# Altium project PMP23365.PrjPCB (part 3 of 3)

## Sheet PMP23365B_SH3.SchDoc
size 558 x 431 mm; Date: Not shown in title block; ApprovedBy: Not shown in title block; CheckedBy: Not shown in title block; Author: Not shown in title block; CompanyName: Not shown in title block; DrawnBy: D Xing; Engineer: Not shown in title block; Organization: Not shown in title block; Address1: Not shown in title block; Address2: Not shown in title block; Address3: Not shown in title block; Address4: Not shown in title block; DocumentNumber: 1; Revision: Use project parameter SCH_Rev; SheetNumber: 3; SheetTotal: 3; PageSetup: Record=PageOptions¦CenterHorizontal=True¦CenterVertical=True¦PrintScale=1.00¦XCorrection=1.00¦YCorrection=1.00¦PrintKind=0¦BorderSize=5000000¦LeftOffset=0¦BottomOffset=0¦Orientation=2¦PaperLength=1000¦PaperWidth=1000¦Scale=100¦PaperSource=15¦PrintQuality=600¦MediaType=1¦DitherType=10¦PaperKind=Letter¦PrintScaleMode=1
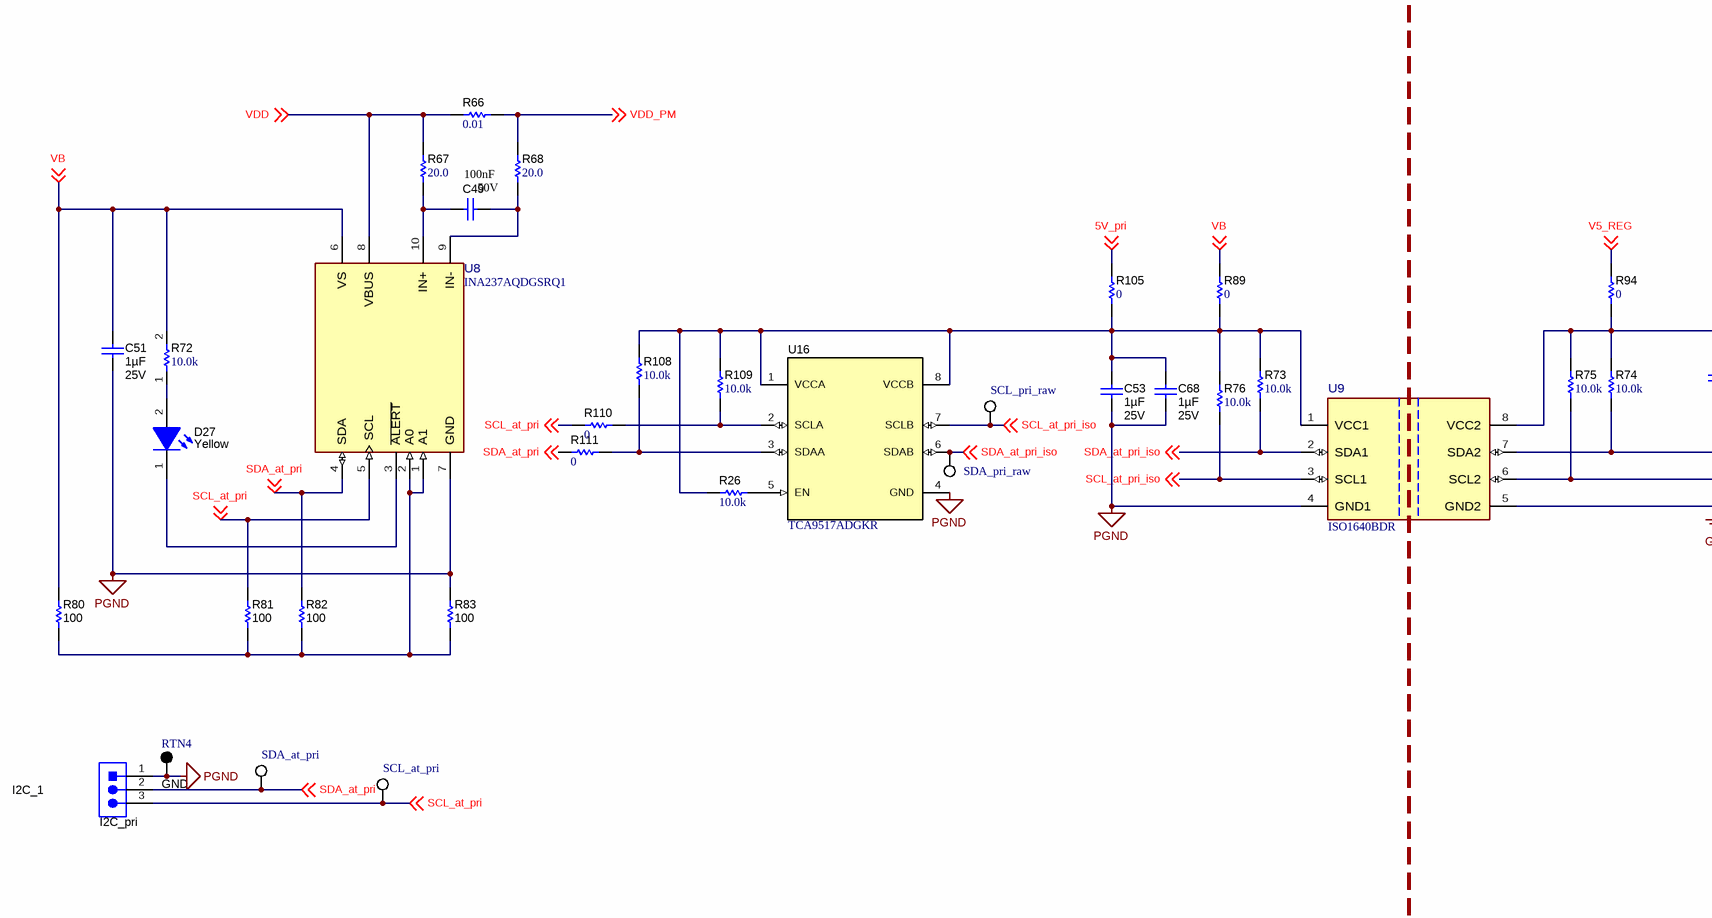
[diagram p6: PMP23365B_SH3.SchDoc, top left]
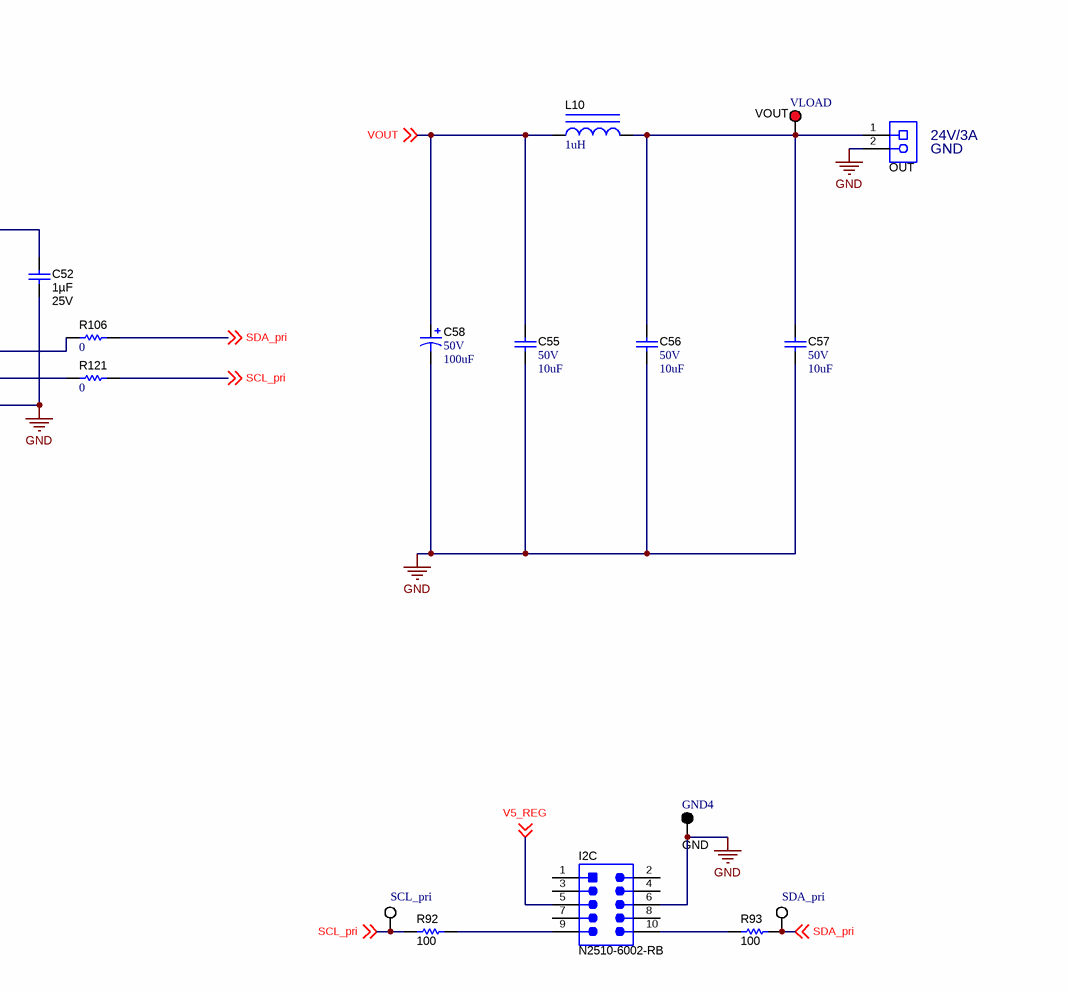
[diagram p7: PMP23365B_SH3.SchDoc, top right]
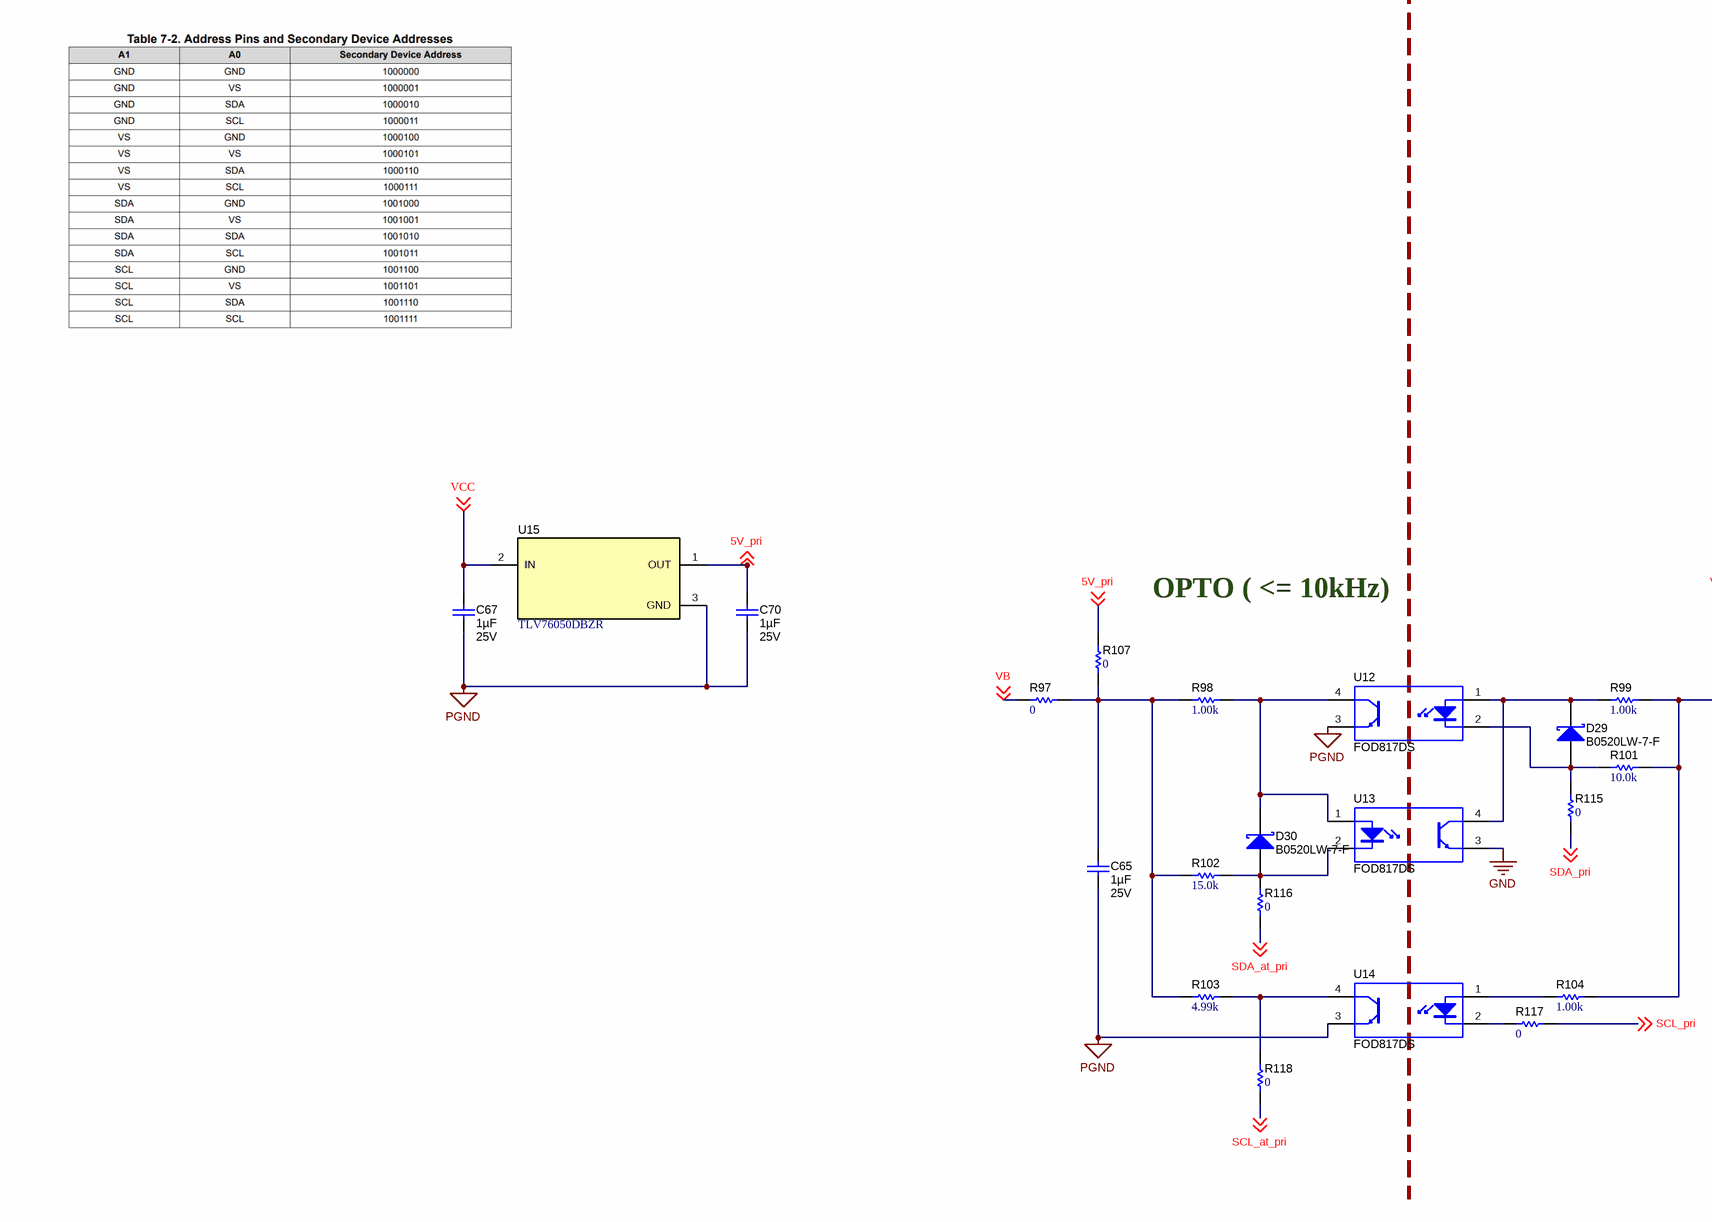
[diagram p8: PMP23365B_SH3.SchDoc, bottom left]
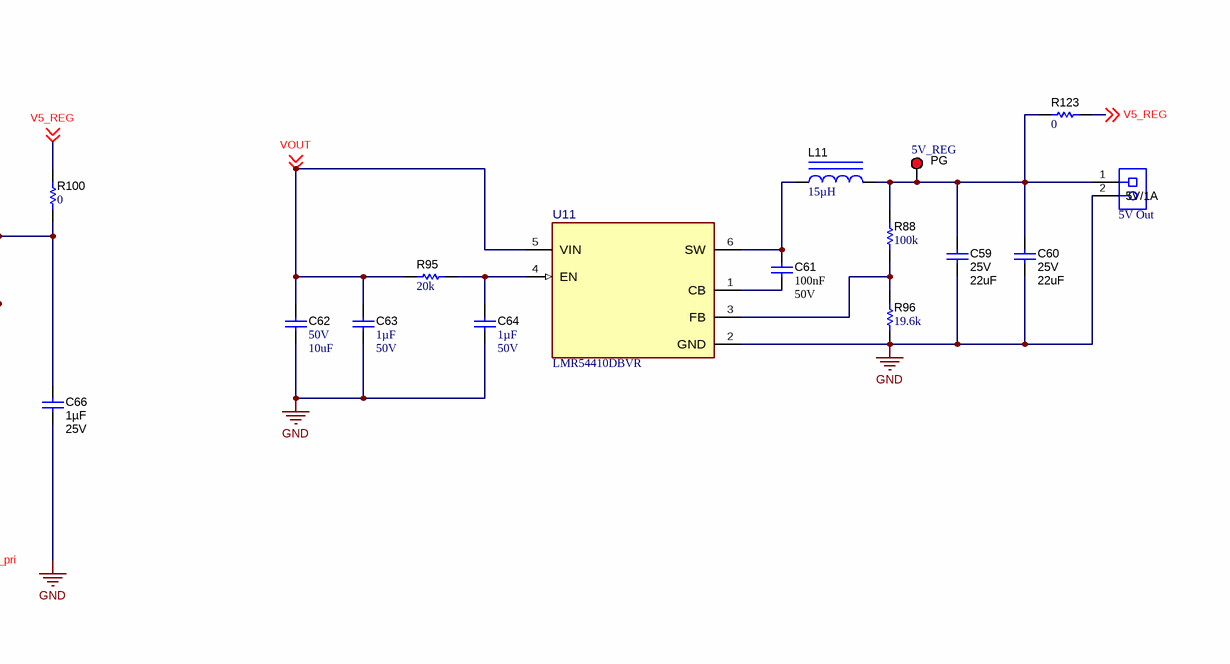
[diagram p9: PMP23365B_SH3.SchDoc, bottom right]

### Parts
5V_Out  CMP-0074913-1  [TERM_BLK_ED555-2DS]  (value not drawn)
5V_REG  PG  [Keystone5000]
C49  Cap_F: 100nF  VDC_V: 50V  [0603]  (hidden comment: 885012206095)
C51  Cap_F: 1µF  VDC_V: 25V  [0603L]  (hidden comment: GRJ188R71E105KE11D)
C52  Cap_F: 1µF  VDC_V: 25V  [0603L]  (hidden comment: GRJ188R71E105KE11D)
C53  Cap_F: 1µF  VDC_V: 25V  [0603L]  (hidden comment: GRJ188R71E105KE11D)
C55  VDC_V: 50V  ValueDisplayed: 10uF  [1210_270]  (hidden comment: GRM32ER61H106KA12L)
C56  VDC_V: 50V  ValueDisplayed: 10uF  [1210_270]  (hidden comment: GRM32ER61H106KA12L)
C57  VDC_V: 50V  ValueDisplayed: 10uF  [1210_270]  (hidden comment: GRM32ER61H106KA12L)
C58  VDC_V: 50V  ValueDisplayed: 100uF  [Panasonic_G]  (hidden comment: EEH-ZC1H101P)
C59  VDC_V: 25V  ValueDisplayed: 22uF  [1210_270]  (hidden comment: GRM32ER71E226KE15L)
C60  VDC_V: 25V  ValueDisplayed: 22uF  [1210_270]  (hidden comment: GRM32ER71E226KE15L)
C61  Cap_F: 100nF  VDC_V: 50V  [0603]  (hidden comment: 885012206095)
C62  VDC_V: 50V  ValueDisplayed: 10uF  [1210_270]  (hidden comment: GRM32ER61H106KA12L)
C63  Cap_F: 1µF  VDC_V: 50V  [0603]  (hidden comment: UMK107AB7105KA-T)
C64  Cap_F: 1µF  VDC_V: 50V  [0603]  (hidden comment: UMK107AB7105KA-T)
C65  Cap_F: 1µF  VDC_V: 25V  [0603L]  (hidden comment: GRJ188R71E105KE11D)
C66  Cap_F: 1µF  VDC_V: 25V  [0603L]  (hidden comment: GRJ188R71E105KE11D)
C67  Cap_F: 1µF  VDC_V: 25V  [0603L]  (hidden comment: GRJ188R71E105KE11D)
C68  Cap_F: 1µF  VDC_V: 25V  [0603L]  (hidden comment: GRJ188R71E105KE11D)
C70  Cap_F: 1µF  VDC_V: 25V  [0603L]  (hidden comment: GRJ188R71E105KE11D)
D27  value Yellow  [WL-SMCW_YELLOW]  (hidden comment: 150060YS75000)
D29  B0520LW-7-F  [SOD-123]
D30  B0520LW-7-F  [SOD-123]
GND4  GND  [Keystone5001]
I2C  N2510-6002-RB  [CONN_2510-6002]
I2C_pri  5-146278-3  [TE_5-146278-3]  (value not drawn)
L10  ValueDisplayed: 1uH  [IHLP-2020CZ]  (hidden comment: IHLP2020CZER1R0M11)
L11  ValueDisplayed: 15µH  [DEM8030C]  (hidden comment: 1273AS-H-150M=P3)
OUT  ED555/2DS  [TERM_BLK_ED555-2DS]  (value not drawn)
R26  ValueDisplayed: 10.0k  [0603]  (hidden comment: M55342K12B10E0T)
R66  ValueDisplayed: 0.01  [WSLHP0805]  (hidden comment: WSL0805R0100FEA18)
R67  ValueDisplayed: 20.0  [0603]  (hidden comment: RC0603FR-0720RL)
R68  ValueDisplayed: 20.0  [0603]  (hidden comment: RC0603FR-0720RL)
R72  ValueDisplayed: 10.0k  [0603]  (hidden comment: M55342K12B10E0T)
R73  ValueDisplayed: 10.0k  [0603]  (hidden comment: M55342K12B10E0T)
R74  ValueDisplayed: 10.0k  [0603]  (hidden comment: M55342K12B10E0T)
R75  ValueDisplayed: 10.0k  [0603]  (hidden comment: M55342K12B10E0T)
R76  ValueDisplayed: 10.0k  [0603]  (hidden comment: M55342K12B10E0T)
R80  ValueDisplayed: 100  [0603L]  (hidden comment: CRCW0603100RFKEA)
R81  ValueDisplayed: 100  [0603L]  (hidden comment: CRCW0603100RFKEA)
R82  ValueDisplayed: 100  [0603L]  (hidden comment: CRCW0603100RFKEA)
R83  ValueDisplayed: 100  [0603L]  (hidden comment: CRCW0603100RFKEA)
R88  ValueDisplayed: 100k  [0603]  (hidden comment: CRCW0603100KFKEA)
R89  ValueDisplayed: 0  [0603]  (hidden comment: ERJ-3GEY0R00V)
R92  ValueDisplayed: 100  [0603L]  (hidden comment: CRCW0603100RFKEA)
R93  ValueDisplayed: 100  [0603L]  (hidden comment: CRCW0603100RFKEA)
R94  ValueDisplayed: 0  [0603]  (hidden comment: ERJ-3GEY0R00V)
R95  ValueDisplayed: 20k  [0603]  (hidden comment: CRCW060320K0JNEA)
R96  ValueDisplayed: 19.6k  [0603]  (hidden comment: CRCW060319K6FKEA)
R97  ValueDisplayed: 0  [0603]  (hidden comment: ERJ-3GEY0R00V)
R98  ValueDisplayed: 1.00k  [0603]  (hidden comment: CRCW06031K00FKEA)
R99  ValueDisplayed: 1.00k  [0603]  (hidden comment: CRCW06031K00FKEA)
R100  ValueDisplayed: 0  [0603]  (hidden comment: ERJ-3GEY0R00V)
R101  ValueDisplayed: 10.0k  [0603]  (hidden comment: M55342K12B10E0T)
R102  ValueDisplayed: 15.0k  [0603]  (hidden comment: RC0603FR-0715KL)
R103  ValueDisplayed: 4.99k  [0603]  (hidden comment: CRCW06034K99FKEAC)
R104  ValueDisplayed: 1.00k  [0603]  (hidden comment: CRCW06031K00FKEA)
R105  ValueDisplayed: 0  [0603]  (hidden comment: ERJ-3GEY0R00V)
R106  ValueDisplayed: 0  [0603]  (hidden comment: ERJ-3GEY0R00V)
R107  ValueDisplayed: 0  [0603]  (hidden comment: ERJ-3GEY0R00V)
R108  ValueDisplayed: 10.0k  [0603]  (hidden comment: M55342K12B10E0T)
R109  ValueDisplayed: 10.0k  [0603]  (hidden comment: M55342K12B10E0T)
R110  ValueDisplayed: 0  [0603]  (hidden comment: ERJ-3GEY0R00V)
R111  ValueDisplayed: 0  [0603]  (hidden comment: ERJ-3GEY0R00V)
R115  ValueDisplayed: 0  [0603]  (hidden comment: ERJ-3GEY0R00V)
R116  ValueDisplayed: 0  [0603]  (hidden comment: ERJ-3GEY0R00V)
R117  ValueDisplayed: 0  [0603]  (hidden comment: ERJ-3GEY0R00V)
R118  ValueDisplayed: 0  [0603]  (hidden comment: ERJ-3GEY0R00V)
R121  ValueDisplayed: 0  [0603]  (hidden comment: ERJ-3GEY0R00V)
R123  ValueDisplayed: 0  [0603]  (hidden comment: ERJ-3GEY0R00V)
RTN4  GND  [Keystone5001]
SCL_at_pri  5002  [Keystone5002]  (value not drawn)
SCL_pri  5002  [Keystone5002]  (value not drawn)
SCL_pri_raw  5002  [Keystone5002]  (value not drawn)
SDA_at_pri  5002  [Keystone5002]  (value not drawn)
SDA_pri  5002  [Keystone5002]  (value not drawn)
SDA_pri_raw  5002  [Keystone5002]  (value not drawn)
U8  INA237AQDGSRQ1  [DGS0010A-MFG]
U9  ISO1640BDR  [D0008A-MFG]
U11  LMR54410DBVR  [DBV0006A-MFG]
U12  FOD817DS  [N04C]
U13  FOD817DS  [N04C]
U14  FOD817DS  [N04C]
U15  TLV76050DBZR  [DBZ0003A_N]
U16  TCA9517ADGKR  [DGK0008A_N]
VLOAD  VOUT  [Keystone5000]

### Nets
GND: 5V_Out.2 C52.2 C55.2 C56.2 C57.2 C58.2(-) C59.1 C60.1 C62.2 C63.2 C64.2 C66.2 GND4.1 I2C.6 OUT.2 R96.1 U9.5(GND2) U11.2(GND) U13.3(E)
PGND: C51.2 C53.2 C65.2 C67.2 C68.2 C70.2 I2C_pri.1 R83.2 RTN4.1 U8.7(GND) U9.4(GND1) U12.3(E) U14.3(E) U15.3(GND) U16.4(GND)
5V_pri: C70.1 R105.1 R107.1 U15.1(OUT) ; off-sheet 5V_pri
SCL_at_pri: I2C_pri.3 R81.2 R110.2 R118.2 SCL_at_pri.1 U8.5(SCL) ; off-sheet SCL_at_pri
SCL_at_pri_iso: R76.1 SCL_pri_raw.1 U9.3(SCL1) U16.7(SCLB) ; off-sheet SCL_at_pri_iso
SCL_pri: R92.2 R117.2 R121.2 SCL_pri.1 ; off-sheet SCL_pri
SDA_at_pri: I2C_pri.2 R82.2 R111.1 R116.2 SDA_at_pri.1 U8.4(SDA) ; off-sheet SDA_at_pri
SDA_at_pri_iso: R73.1 SDA_pri_raw.1 U9.2(SDA1) U16.6(SDAB) ; off-sheet SDA_at_pri_iso
SDA_pri: R93.1 R106.2 R115.1 SDA_pri.1 ; off-sheet SDA_pri
V5_REG: I2C.5 R94.2 R100.1 R123.1 ; off-sheet V5_REG
VB: C51.1 R72.2 R80.2 R89.2 R97.2 U8.6(VS) ; off-sheet VB
VCC: C67.1 U15.2(IN) ; off-sheet VCC
VDD: R66.1 R67.2 U8.8(VBUS) ; off-sheet VDD
VDD_PM: R66.2 R68.2 ; off-sheet VDD_PM
VOUT: C55.1 C58.1(+) C62.1 C63.1 L10.1 R95.2 U11.5(VIN) ; off-sheet VOUT
Net5V_Out_1: 5V_Out.1 5V_REG.1 C59.2 C60.2 L11.2 R88.2 R123.2
NetC49_1: C49.1 R67.1 U8.10(IN+)
NetC49_2: C49.2 R68.1 U8.9(IN-)
NetC52_1: C52.1 R74.1 R75.1 R94.1 U9.8(VCC2)
NetC53_1: C53.1 C68.1 R26.2 R73.2 R76.2 R89.1 R105.2 R108.2 R109.2 U9.1(VCC1) U16.1(VCCA) U16.8(VCCB)
NetC56_1: C56.1 C57.1 L10.2 OUT.1 VLOAD.1
NetC61_1: C61.1 U11.1(CB)
NetC61_2: C61.2 L11.1 U11.6(SW)
NetC64_1: C64.1 R95.1 U11.4(EN)
NetC65_1: C65.1 R97.1 R98.1 R102.1 R103.1 R107.2
NetC66_1: C66.1 R99.2 R100.2 R101.2 R104.2
NetD27_1: D27.1(K) U8.3(~{ALERT})
NetD27_2: D27.2(A) R72.1
NetD29_1: D29.1(K) R99.1 U12.1(A) U13.4(C)
NetD29_2: D29.2(A) R101.1 R115.2 U12.2(K)
NetD30_1: D30.1(K) R98.2 U12.4(C) U13.1(A)
NetD30_2: D30.2(A) R102.2 R116.1 U13.2(K)
NetI2C_9: I2C.9 R92.1
NetI2C_10: I2C.10 R93.2
NetR26_1: R26.1 U16.5(EN)
NetR74_2: R74.2 R106.1 U9.7(SDA2)
NetR75_2: R75.2 R121.1 U9.6(SCL2)
NetR80_1: R80.1 R81.1 R82.1 R83.1 U8.1(A1) U8.2(A0)
NetR88_1: R88.1 R96.2 U11.3(FB)
NetR103_2: R103.2 R118.1 U14.4(C)
NetR104_1: R104.1 U14.1(A)
NetR108_1: R108.1 R111.2 U16.3(SDAA)
NetR109_1: R109.1 R110.1 U16.2(SCLA)
NetR117_1: R117.1 U14.2(K)

Not connected (* = marked no-connect by the designer): I2C 1 2 3 4 7 8

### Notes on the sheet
- (near OUT) 24V/3A
- (near OUT) GND
- (near I2C_pri) I2C_1
- OPTO ( <= 10kHz)
- (near 5V_Out) 5V/1A

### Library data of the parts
5V_Out = CMP-0074913-1: Terminal Block, 3.5mm Pitch, 2x1, TH; PartNumber: ED555/2DS; Manufacturer: On-Shore Technology; Cert_VDE: Y; CNHeader: False; Current_A: 6A; Green_Lifecycle: Active; Shrouded: N; Gender: Female; Green_REACh: Passed; Voltage_V: 150V; Row_Count: 1; Pitch_mm: 3.5; ContactFinish: Brass; CT: True
5V_REG VLOAD = CMP-0055137-2: Test Point, Miniature, Red, TH; Manufacturer: Keystone Electronics; Green_REACh: Passed; Green_Lifecycle: Active; ContactFinish: Silver; CNHeader: FALSE; CT: TRUE
C49 C61 = CMP-0006837-3: CAP, CERM, 0.1 uF, 50 V, +/- 10%, X7R, 0603; Manufacturer: Wurth Elektronik; TaMin_C: -55°C; Polarized: N; SizeAreaWB_mm2: 4.68; Value1: Unknown; U/M: EA; Value: 0.1uF; TaMax_C: 125°C; SizeZ_mm: 1; SizeX_mm: 1.6; SizeY_mm: 0.8; SizeArea_mm2: 1.28; AEC Category: Q200
C51-C53 C65-C68 C70 = CMP-0079720-1: CAP, CERM, 1 µF, 25 V,+/- 10%, X7R, 0603; Manufacturer: MuRata; TaMin_C: -55°C; Polarized: N; SizeAreaWB_mm2: 4.68; U/M: EA; Value: 1uF; TaMax_C: 125°C; SizeZ_mm: 1; SizeX_mm: 1.6; SizeY_mm: 0.8; Cap_Case: 0603; SizeArea_mm2: 1.28; AEC Category: Q200
C55-C57 C62 = CMP-0009214-2: CAP, CERM, 10 uF, 50 V, +/- 10%, X5R, 1210; Manufacturer: MuRata; TaMin_C: -55°C; Polarized: N; SizeAreaWB_mm2: 14.7; Value1: Unknown; U/M: EA; Value: 10uF; TaMax_C: 85°C; SizeZ_mm: 2.7; SizeX_mm: 3.2; SizeY_mm: 2.5; Cap_Case: 1210; SizeArea_mm2: 8; Cap_F: 10µF; AEC Category: Q200
C58 = CMP-0064994-2: CAP, Polymer Hybrid, 100 uF, 50 V,+/- 20%, 0.028 ohm, AEC-Q200 Grade 1, D10xL10.2mm SMD; Manufacturer: Panasonic; TaMin_C: -55°C; ESR_ohm: 28m; Polarized: Y; SizeAreaWB_mm2: 151.29; Value: 100uF; TaMax_C: 125°C; SizeZ_mm: 10.5; SizeX_mm: 10.3; Cap_Case: 10x10.2mm; SizeArea_mm2: 106.09; CompType: Capacitor; Cap_F: 100µF; IRMS_A: 1.6A; AEC Grade: 1; AEC Category: Q200
C59 C60 = CMP-0009224-2: CAP, CERM, 22 uF, 25 V, +/- 10%, X7R, 1210; Manufacturer: MuRata; TaMin_C: -55°C; Polarized: N; SizeAreaWB_mm2: 14.7; Value1: Unknown; U/M: EA; Value: 22uF; TaMax_C: 125°C; SizeZ_mm: 2.7; SizeX_mm: 3.2; SizeY_mm: 2.5; Cap_Case: 1210; SizeArea_mm2: 8; Cap_F: 22µF; AEC Category: Q200
C63 C64 = CMP-0007508-5: CAP, CERM, 1 uF, 50 V, +/- 10%, X7R, 0603; Manufacturer: Taiyo Yuden; TaMin_C: -55°C; Polarized: N; SizeAreaWB_mm2: 4.68; Value1: Unknown; U/M: EA; Value: 1uF; TaMax_C: 125°C; SizeZ_mm: 1; SizeX_mm: 1.6; SizeY_mm: 0.8; SizeArea_mm2: 1.28; AEC Category: Q200
D27 = CMP-0002892-3: LED, Yellow, SMD; Manufacturer: Wurth Elektronik; Value1: W; Vf_V: 2V; Type: AlInGaP; Io_A: 20mA
D29 D30 = CMP-0080707-2: Diode, Schottky, 20 V, 0.5 A, SOD-123; Manufacturer: Diodes Inc.; SizeY_mm: 1.7; Vf_V: 330mV; Vr_V: 20V; SizeZ_mm: 1.35; AEC Qualified: N; SizeAreaWB_mm2: 13.095; AEC Category: Q101; Value: 20V; Value1: 0.5A; Io_A: 500mA; Value2: 0.33V; TJmax_C: 125°C; SizeArea_mm2: 6.545; SizeX_mm: 3.85
GND4 RTN4 = CMP-0055138-2: Test Point, Miniature, Black, TH; Manufacturer: Keystone Electronics; ContactFinish: Silver; CNHeader: FALSE; Green_Lifecycle: Active; Green_REACh: Passed; CT: TRUE
I2C = CMP-0055448-2: Header (shrouded), 100mil, 5x2, High-Temperature, Gold, TH; Manufacturer: 3M; Green_Lifecycle: Active; Green_REACh: Passed
I2C_pri = CMP-0054951-1: Header, 100mil, 3x1, Tin, TH; Manufacturer: TE Connectivity; CNHeader: TRUE; Green_Lifecycle: Active; Green_REACh: Passed; CT: FALSE
L10 = CMP-0063313-2: Inductor, Shielded Drum Core, Powdered Iron, 1 uH, 6.5 A, 0.011 ohm, SMD; Manufacturer: Vishay-Dale; Isat: 6.5A @ 20% inductance drop; Irms: 10A @ 40C rise; Green_Lifecycle: Active; SizeAreaWB_mm2: 53.7782; DCR_ohm: 11m; Green_REACh: Passed; Value: 1uH; Imax_A: 6.5A; SizeZ_mm: 3; SizeX_mm: 5.49; SizeY_mm: 5.18; SizeArea_mm2: 28.4382; Ind_H: 1µH; AEC Category: Q200
L11 = CMP-0080041-1: Inductor, Shielded, Ferrite, 15 µH, 2.4 A, 0.078 ohm, SMD; Manufacturer: MuRata; SizeAreaWB_mm2: 100; Irms: 2.6A @ 40C rise; SizeArea_mm2: 64; AEC Qualified: N; AEC Category: Q200; Value: 15uH; SizeZ_mm: 3; Imax_A: 2.4A; SizeY_mm: 8; Isat: 2.4A @ 30% inductance drop; DCR_ohm: 78m
OUT = CMP-0074913-1: Terminal Block, 3.5mm Pitch, 2x1, TH; Manufacturer: On-Shore Technology; Cert_VDE: Y; CNHeader: False; Current_A: 6A; Green_Lifecycle: Active; Shrouded: N; Gender: Female; Green_REACh: Passed; Voltage_V: 150V; Row_Count: 1; Pitch_mm: 3.5; ContactFinish: Brass; CT: True
R26 R72-R76 R101 R108 R109 = CMP-0080488-1: RES, 10.0 k, 1%, 0.1 W, 0603; Manufacturer: TT Electronics/IRC; Power_W: 100mW; TempCo: 100 ppm/C; SizeAreaWB_mm2: 4.68; Value_Code: 10k0; Value: 10.0k; EIA_Code: E96; Res_ohm: 10k; SizeX_mm: 1.6; SizeY_mm: 0.8; SizeZ_mm: 1; Value2: 0.1W; SizeArea_mm2: 1.28; AEC Qualified: N; AEC Category: Q200
R66 = CMP-0021980-1: RES, 0.01, 1%, 0.25 W, AEC-Q200 Grade 0, 0805; Manufacturer: Vishay-Dale; Power_W: 250mW; TempCo: 75 ppm/C; Value_Code: R010; U/M: EA; Value: 0.01; EIA_Code: E96; Res_ohm: 10m; SizeX_mm: 2.03; SizeY_mm: 1.27; SizeZ_mm: 0.51; Value2: 0.25W; SizeArea_mm2: 2.5781; AEC Qualified: Y; AEC Grade: 0; AEC Category: Q200
R67 R68 = CMP-0022908-4: RES, 20.0, 1%, 0.1 W, 0603; Manufacturer: Yageo; Power_W: 100mW; TempCo: 100 ppm/C; Value_Code: 20R0; Value: 20.0; EIA_Code: E96; Res_ohm: 20; SizeX_mm: 1.6; SizeY_mm: 0.8; SizeZ_mm: 1; Value2: 0.1W; SizeArea_mm2: 1.28; AEC Qualified: N; VDC_V: 75V; AEC Category: Q200; SizeAreaWB_mm2: 4.68
R80-R83 R92 R93 = CMP-0021991-4: RES, 100, 1%, 0.1 W, AEC-Q200 Grade 0, 0603; Manufacturer: Vishay-Dale; Power_W: 100mW; TempCo: 100 ppm/C; Value_Code: 100R; Value: 100; EIA_Code: E96; SizeX_mm: 1.6; SizeY_mm: 0.8; SizeZ_mm: 1; Value2: 0.1W; SizeArea_mm2: 1.28; AEC Qualified: Y; VDC_V: 75V; AEC Category: Q200; AEC Grade: 0
R88 = CMP-0021990-4: RES, 100 k, 1%, 0.1 W, AEC-Q200 Grade 0, 0603; Manufacturer: Vishay-Dale; Power_W: 100mW; TempCo: 100 ppm/C; Value: 100k; EIA_Code: E96; SizeX_mm: 1.6; SizeY_mm: 0.8; SizeZ_mm: 1; Value2: 0.1W; SizeArea_mm2: 1.28; AEC Qualified: Y; VDC_V: 75V; AEC Category: Q200; AEC Grade: 0
R89 R94 R97 R100 R105-R107 R110 R111 R115-R118 R121 R123 = CMP-0025874-4: RES, 0, 5%, 0.1 W, AEC-Q200 Grade 0, 0603; Manufacturer: Panasonic; Power_W: 100mW; TempCo: 600 ppm/C; Value_Code: 0000; Value: 0; EIA_Code: E24; SizeX_mm: 1.6; SizeY_mm: 0.8; SizeZ_mm: 1; Value2: 0.1W; SizeArea_mm2: 1.28; AEC Qualified: Y; VDC_V: 50V; AEC Category: Q200; SizeAreaWB_mm2: 4.68
R95 = CMP-0025753-1: RES, 20 k, 5%, 0.1 W, 0603; Manufacturer: Vishay-Dale; Power_W: 100mW; TempCo: 200 ppm/C; Value_Code: 20k0; U/M: EA; Value: 20k; EIA_Code: E24; SizeX_mm: 1.6; SizeY_mm: 0.8; SizeZ_mm: 1; Value2: 0.1W; SizeArea_mm2: 1.28; VDC_V: 75V; AEC Category: Q200
R96 = CMP-0022106-2: RES, 19.6 k, 1%, 0.1 W, 0603; Manufacturer: Vishay-Dale; Power_W: 100mW; TempCo: 100 ppm/C; Value_Code: 19k6; U/M: EA; Value: 19.6k; EIA_Code: E96; SizeX_mm: 1.6; SizeY_mm: 0.8; SizeZ_mm: 1; Value2: 0.1W; SizeArea_mm2: 1.28; VDC_V: 75V; AEC Category: Q200
R98 R99 R104 = CMP-0022109-5: RES, 1.00 k, 1%, 0.1 W, AEC-Q200 Grade 0, 0603; Manufacturer: Vishay-Dale; Power_W: 100mW; TempCo: 100 ppm/C; Value_Code: 1k00; Value: 1.00k; EIA_Code: E96; Res_ohm: 1k; SizeX_mm: 1.6; SizeY_mm: 0.8; SizeZ_mm: 1; Value2: 0.1W; SizeArea_mm2: 1.28; AEC Qualified: Y; VDC_V: 75V; AEC Category: Q200; AEC Grade: 0
R102 = CMP-0022816-5: RES, 15.0 k, 1%, 0.1 W, 0603; Manufacturer: Yageo; Power_W: 100mW; TempCo: 100 ppm/C; Value_Code: 15k0; Value: 15.0k; EIA_Code: E96; Res_ohm: 15k; SizeX_mm: 1.6; SizeY_mm: 0.8; SizeZ_mm: 1; Value2: 0.1W; SizeArea_mm2: 1.28; AEC Qualified: N; VDC_V: 75V; AEC Category: Q200; SizeAreaWB_mm2: 4.68
R103 = CMP-0082533-1: RES, 4.99 k, 1%, 0.1 W, 0603; Manufacturer: Vishay-Dale; Power_W: 100mW; TempCo: 100 ppm/C; SizeAreaWB_mm2: 4.68; Value_Code: 4k99; Value: 4.99k; EIA_Code: E96; SizeX_mm: 1.6; SizeY_mm: 0.8; SizeZ_mm: 1; Value2: 0.1W; SizeArea_mm2: 1.28; AEC Qualified: N; VDC_V: 75V; AEC Category: Q200
SCL_at_pri SCL_pri SCL_pri_raw SDA_at_pri SDA_pri SDA_pri_raw = CMP-0055139-1: Test Point, Miniature, White, TH; Manufacturer: Keystone; CNHeader: FALSE; Green_Lifecycle: Active; Green_REACh: Passed; ContactFinish: Silver; CT: TRUE
U8 = CMP-0088571-2: High-Voltage, Zero-Drift, 16-Bit ADC, I 2C, Bidirectional Shunt Current, Bus Voltage, Power, and Temperature Monitor; Manufacturer: Texas Instruments; Number Of Converters: 1; AEC Category: Q200; CompType: IC; Standoff Height: 0.05mm; Interface: I2C; Data Polarity: Differential; SizeZ_mm: 1.1mm
U9 = CMP-0091761-1: I²C Digital Isolator 3000Vrms 2 Channel  50kV/µs CMTI 8-SOIC (0.154", 3.90mm Width); Manufacturer: Texas Instruments; TaMin_C: -40°C; AEC Qualified: No; Standoff Height: 0.11mm; Min Supply Voltage: 2.25V; SizeZ_mm: 1.75mm; Nominal Supply Current: 2.7-5.3mA; Interface: I2C; TaMax_C: +125°C; TJmax_C: +150°C; Max Supply Voltage: 5.5V
U11 = CMP-0093105-2: Buck Converter, Adjustable, 4V-36V Input, 1-28V 1A Output, SOT23-6; Manufacturer: Texas Instruments; SizeZ_mm: 1.45mm; Max Supply Voltage: 36V; Standoff Height: 0mm; Min Supply Voltage: 4V; Number Of Outputs: 1; TJmax_C: +150°C; Nominal Supply Current: 80uA; Max Duty Cycle: 98%; CompType: IC; Switching Frequency: 700kHz; AEC Qualified: No; Output Type: AdjustableProgrammable; AEC Category: Q200
U12-U14 = CMP-0006165-2: Optocoupler, 5 kV, 300-600% CTR, SMT; Manufacturer: Fairchild Semiconductor; CTR (Max): 600%; CTR (Min): 300%; Voltage_Isolation_Vrms: 5kV
U15 = CMP-0074892-1: 100-mA, 30-V, Fixed-Output, Linear-Voltage Regulator, DBZ0003A (SOT-23-3); Alternate PartNumber: TLV76050DBZT; Alternate Manufacturer: Texas Instruments; SizeAreaWB_mm2: 14.0; SizeZ_mm: 1.12; SizeX_mm: 2.5; SizeY_mm: 3.0; SizeArea_mm2: 7.5; CompType: IC; AEC Qualified: N; AEC Category: Q200
U16 = CMP-0065788-2: Level-Translating I2C Bus Repeater, DGK0008A (VSSOP-8); Alternate Manufacturer: Texas Instruments; SizeAreaWB_mm2: 23.6; SizeZ_mm: 1.1; SizeX_mm: 4.9; SizeY_mm: 3; SizeArea_mm2: 14.7; CompType: IC; AEC Category: Q200; AEC Qualified: N

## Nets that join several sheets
GND: PMP23365B_SH2 (29 pins), PMP23365B_SH3 (19 pins)
PGND: PMP23365B_SH1 (5 pins), PMP23365B_SH2 (46 pins), PMP23365B_SH3 (15 pins)
APD: PMP23365B_SH1 (APD1.1 APD2.2 R10.1 R11.2), PMP23365B_SH2 (Q12.1 U1.5)
VB: PMP23365B_SH1 (APD2.3), PMP23365B_SH2 (7 pins), PMP23365B_SH3 (6 pins)
VCC: PMP23365B_SH2 (10 pins), PMP23365B_SH3 (C67.1 U15.2)
VDD: PMP23365B_SH1 (C11.1 D1.1 L4.2), PMP23365B_SH2 (7 pins), PMP23365B_SH3 (R66.1 R67.2 U8.8)
VDD_PM: PMP23365B_SH2 (C22.1 L7.1), PMP23365B_SH3 (R66.2 R68.2)
VOUT: PMP23365B_SH2 (6 pins), PMP23365B_SH3 (7 pins)
VSS: PMP23365B_SH1 (C11.2 L6.2), PMP23365B_SH2 (15 pins)

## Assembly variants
001: not fitted C18 C32 C40 C50 C54 D10 D19 D28 I2C_sec L2 L5 R26 R28 R33 R56 R70 R71 R77 R78 R79 R81 R82 R83 R84 R85 R86 R87 R89 R90 R91 R94 R97 R105 R110 R111 U10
